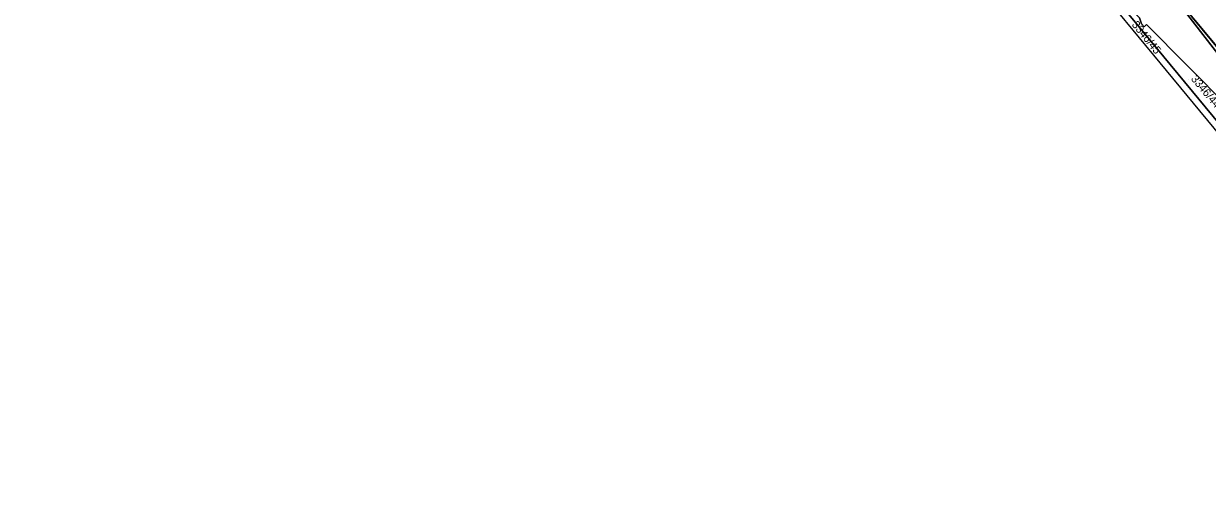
# Model space of a CAD drawing. Extents: x -262715 to -259381, y -1237238 to -1231182.
# Drawn here: x -262455.8 to -262159.9, y -1235692.8 to -1235578.3 of the extents above; entities that cross this region are included whole.
import ezdxf

# ---------------------------------------------------------------- set-up
doc = ezdxf.new("R2010")
doc.units = 0
for name, color, linetype in [('body_kn', 7, 'Continuous'), ('katuz_linie', 7, 'Continuous'), ('kladpar_druhypozemkov', 7, 'Continuous'), ('kladpar_hranice', 7, 'Continuous'), ('kladpar_parcelnecisla', 7, 'Continuous'), ('kladpar_plochy', 7, 'Continuous'), ('zuob_linie', 7, 'Continuous'), ('zuob_plochy', 7, 'Continuous')]:
    doc.layers.add(name, color=color, linetype=linetype)

msp = doc.modelspace()

# ---------------------------------------------------------------- linework, layer by layer
at = {"layer": 'body_kn'}
for p, q in [((-262176.4, -1235578.34), (-262176.4, -1235578.34)), ((-262175.72, -1235579.05), (-262175.72, -1235579.05)), ((-262175.12, -1235578.48), (-262175.12, -1235578.48))]:
    msp.add_line(p, q, dxfattribs=at)
at = {"layer": 'katuz_linie'}
msp.add_lwpolyline([(-262158.19, -1235604.44), (-262202.3, -1235550.98)], dxfattribs=at)
at = {"layer": 'kladpar_druhypozemkov'}
msp.add_line((-262164.63, -1235592.13), (-262164.63, -1235592.13), dxfattribs=at)
at = {"layer": 'kladpar_hranice'}
for p, q in [((-262100.82, -1235659.07), (-262455.78, -1235199.04)), ((-262455.78, -1235199.04), (-262100.82, -1235659.07))]:
    msp.add_line(p, q, dxfattribs=at)
for points in [[(-262085.74, -1235647.92), (-262132.19, -1235591.56), (-262158.37, -1235565.14), (-262189.52, -1235527.36), (-262193.4, -1235524.22), (-262196.66, -1235523.62), (-262199.71, -1235525.48), (-262200.9, -1235528.44), (-262200.29, -1235532.33), (-262136.59, -1235609.33), (-262113.31, -1235633.36), (-262095.72, -1235654.36)], [(-262095.72, -1235654.36), (-262113.31, -1235633.36), (-262136.59, -1235609.33), (-262200.29, -1235532.33), (-262200.9, -1235528.44), (-262199.71, -1235525.48), (-262196.66, -1235523.62), (-262193.4, -1235524.22), (-262189.52, -1235527.36), (-262158.37, -1235565.14), (-262132.19, -1235591.56), (-262085.74, -1235647.92)], [(-262154.73, -1235599.11), (-262175.12, -1235578.48), (-262175.72, -1235579.05), (-262176.4, -1235578.34), (-262176.86, -1235576.83), (-262177.88, -1235575.79), (-262191.68, -1235559.21), (-262192.27, -1235559.69), (-262192.86, -1235558.87), (-262193.13, -1235557.44), (-262200.69, -1235548.44), (-262203.8, -1235546.57), (-262205.43, -1235546)], [(-262203.8, -1235546.57), (-262200.69, -1235548.44), (-262193.13, -1235557.44), (-262192.86, -1235558.87), (-262192.27, -1235559.69), (-262191.68, -1235559.21), (-262177.88, -1235575.79), (-262176.86, -1235576.83), (-262176.4, -1235578.34), (-262175.72, -1235579.05), (-262175.12, -1235578.48), (-262154.73, -1235599.11)], [(-262156.86, -1235603.38), (-262203.8, -1235546.57)], [(-262203.8, -1235546.57), (-262156.86, -1235603.38), (-262092.38, -1235681.54), (-262091.43, -1235681.94), (-262090.55, -1235681.64), (-262088.57, -1235680.02), (-262085.28, -1235684.03), (-262087.26, -1235685.53), (-262087.81, -1235686.33), (-262087.74, -1235687.21), (-262084, -1235691.81), (-262085.41, -1235692.75), (-262093.33, -1235683.03), (-262100.71, -1235674.09), (-262118.21, -1235652.89), (-262158.19, -1235604.44), (-262202.3, -1235550.98)]]:
    msp.add_lwpolyline(points, dxfattribs=at)
at = {"layer": 'kladpar_plochy'}
for p, q in [((-262200.29, -1235532.33), (-262136.59, -1235609.33)), ((-262176.4, -1235578.34), (-262176.86, -1235576.83)), ((-262175.72, -1235579.05), (-262176.4, -1235578.34)), ((-262175.12, -1235578.48), (-262175.72, -1235579.05)), ((-262154.73, -1235599.11), (-262175.12, -1235578.48))]:
    msp.add_line(p, q, dxfattribs=at)
for points in [[(-262095.72, -1235654.36), (-262113.31, -1235633.36), (-262136.59, -1235609.33), (-262200.29, -1235532.33), (-262200.9, -1235528.44), (-262199.71, -1235525.48), (-262196.66, -1235523.62), (-262193.4, -1235524.22), (-262189.52, -1235527.36), (-262158.37, -1235565.14), (-262132.19, -1235591.56), (-262085.74, -1235647.92), (-262088.37, -1235645.31), (-262093.72, -1235649.67), (-262092.3, -1235651.1)], [(-262203.8, -1235546.57), (-262156.86, -1235603.38), (-262092.38, -1235681.54), (-262091.43, -1235681.94), (-262090.55, -1235681.64), (-262088.57, -1235680.02), (-262085.28, -1235684.03), (-262087.26, -1235685.53), (-262087.81, -1235686.33), (-262087.74, -1235687.21), (-262084, -1235691.81), (-262085.41, -1235692.75), (-262093.33, -1235683.03), (-262100.71, -1235674.09), (-262118.21, -1235652.89), (-262158.19, -1235604.44), (-262202.3, -1235550.98), (-262205.43, -1235546)]]:
    msp.add_lwpolyline(points, close=True, dxfattribs=at)
msp.add_lwpolyline([(-262156.86, -1235603.38), (-262203.8, -1235546.57), (-262200.69, -1235548.44), (-262193.13, -1235557.44), (-262192.86, -1235558.87), (-262192.27, -1235559.69), (-262191.68, -1235559.21), (-262177.88, -1235575.79), (-262176.86, -1235576.83), (-262176.4, -1235578.34), (-262175.72, -1235579.05), (-262175.12, -1235578.48), (-262154.73, -1235599.11)], dxfattribs=at)
at = {"layer": 'zuob_linie'}
msp.add_lwpolyline([(-262158.19, -1235604.44), (-262202.3, -1235550.98)], dxfattribs=at)
at = {"layer": 'zuob_plochy'}
msp.add_lwpolyline([(-262158.19, -1235604.44), (-262202.3, -1235550.98)], dxfattribs=at)

# ---------------------------------------------------------------- texts
at = {"layer": 'kladpar_parcelnecisla'}
for s, rotation, p in [('3346/45', 309, (-262178.93, -1235578.56)), ('3346/44', 310, (-262164.14, -1235592.15))]:
    msp.add_text(s, height=2, rotation=rotation, dxfattribs=at).set_placement(p)

doc.saveas('drawing.dxf')
